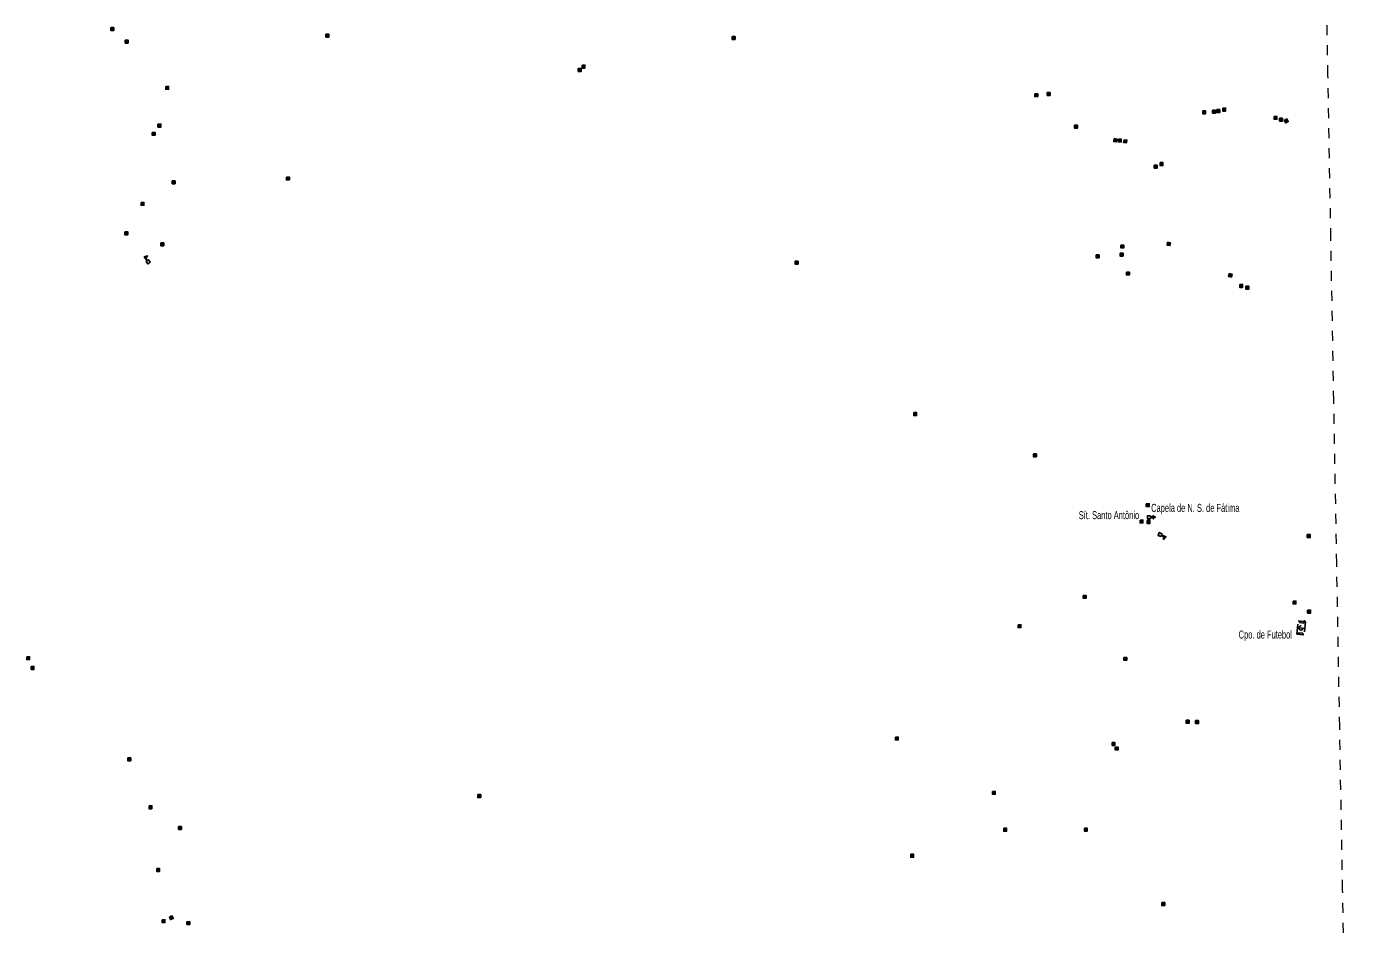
# Model space of a CAD drawing. Extents: x 220.8 to 246.7, y 7287.6 to 7315.8.
# Drawn here: x 233.32 to 246.65, y 7297.47 to 7306.49 of the extents above; entities that cross this region are included whole.
import ezdxf
from ezdxf.enums import TextEntityAlignment as Align

# ---------------------------------------------------------------- set-up
doc = ezdxf.new("R2010")
doc.units = 0
doc.header["$LTSCALE"] = 0.032
doc.header["$PDMODE"] = 32
doc.header["$PDSIZE"] = 0.016
doc.linetypes.add('MEDIUM_DASHED', pattern=[4.5, 3, -1.5])
doc.linetypes.add('SHORT_DASHED', pattern=[2.7, 1.5, -1.2])
for name, color, linetype, lineweight in [('14', 7, 'MEDIUM_DASHED', 25), ('2', 7, 'Continuous', 25), ('4', 7, 'Continuous', 25), ('58', 7, 'SHORT_DASHED', 13), ('6', 7, 'Continuous', 25)]:
    doc.layers.add(name, color=color, linetype=linetype, lineweight=lineweight)
doc.layers.add('61', color=7, linetype='Continuous')

msp = doc.modelspace()

# ---------------------------------------------------------------- hatches: boundary and pattern name
at = {"layer": '2'}
for points in [[(234.163, 7306.4822), (234.192, 7306.4822), (234.192, 7306.4532), (234.163, 7306.4532)], [(234.3069, 7306.3565), (234.3359, 7306.3565), (234.3359, 7306.3275), (234.3069, 7306.3275)], [(236.3128, 7306.416), (236.3418, 7306.416), (236.3418, 7306.387), (236.3128, 7306.387)], [(240.3724, 7306.3926), (240.4014, 7306.3926), (240.4014, 7306.3636), (240.3724, 7306.3636)], [(238.8349, 7306.0722), (238.8639, 7306.0722), (238.8639, 7306.0432), (238.8349, 7306.0432)], [(238.8727, 7306.1069), (238.9017, 7306.1069), (238.9017, 7306.0779), (238.8727, 7306.0779)], [(234.7115, 7305.8939), (234.7405, 7305.8939), (234.7405, 7305.8649), (234.7115, 7305.8649)], [(243.3974, 7305.8206), (243.4264, 7305.8206), (243.4264, 7305.7916), (243.3974, 7305.7916)], [(243.5214, 7305.8325), (243.5504, 7305.8325), (243.5504, 7305.8035), (243.5214, 7305.8035)], [(245.0755, 7305.6496), (245.1045, 7305.6496), (245.1045, 7305.6206), (245.0755, 7305.6206)], [(245.1738, 7305.6557), (245.2028, 7305.6557), (245.2028, 7305.6267), (245.1738, 7305.6267)], [(245.2168, 7305.6619), (245.2458, 7305.6619), (245.2458, 7305.6329), (245.2168, 7305.6329)], [(245.2752, 7305.6772), (245.3042, 7305.6772), (245.3042, 7305.6482), (245.2752, 7305.6482)], [(234.6341, 7305.517), (234.6631, 7305.517), (234.6631, 7305.488), (234.6341, 7305.488)], [(245.7883, 7305.5943), (245.8173, 7305.5943), (245.8173, 7305.5653), (245.7883, 7305.5653)], [(245.8436, 7305.5758), (245.8726, 7305.5758), (245.8726, 7305.5468), (245.8436, 7305.5468)], [(245.8912, 7305.5544), (245.9166, 7305.5685), (245.9307, 7305.5431), (245.9053, 7305.529)], [(234.5767, 7305.4346), (234.6057, 7305.4346), (234.6057, 7305.4056), (234.5767, 7305.4056)], [(243.7956, 7305.5058), (243.8246, 7305.5058), (243.8246, 7305.4768), (243.7956, 7305.4768)], [(244.1905, 7305.3718), (244.2191, 7305.3674), (244.2147, 7305.3387), (244.186, 7305.3432)], [(244.2329, 7305.3681), (244.2619, 7305.3681), (244.2619, 7305.3391), (244.2329, 7305.3391)], [(244.289, 7305.3614), (244.3176, 7305.357), (244.3132, 7305.3283), (244.2845, 7305.3328)], [(244.6495, 7305.1319), (244.6785, 7305.1319), (244.6785, 7305.1029), (244.6495, 7305.1029)], [(235.9185, 7304.9875), (235.9475, 7304.9875), (235.9475, 7304.9585), (235.9185, 7304.9585)], [(244.5905, 7305.1057), (244.6195, 7305.1057), (244.6195, 7305.0767), (244.5905, 7305.0767)], [(234.7767, 7304.9495), (234.8057, 7304.9495), (234.8057, 7304.9205), (234.7767, 7304.9205)], [(234.465, 7304.7345), (234.494, 7304.7345), (234.494, 7304.7055), (234.465, 7304.7055)], [(234.3027, 7304.4404), (234.3317, 7304.4404), (234.3317, 7304.4114), (234.3027, 7304.4114)], [(234.6625, 7304.3307), (234.6915, 7304.3307), (234.6915, 7304.3017), (234.6625, 7304.3017)], [(244.725, 7304.3365), (244.7535, 7304.3314), (244.7484, 7304.3029), (244.7199, 7304.3079)], [(244.0104, 7304.2097), (244.0394, 7304.2097), (244.0394, 7304.1807), (244.0104, 7304.1807)], [(244.2502, 7304.2273), (244.2792, 7304.2273), (244.2792, 7304.1983), (244.2502, 7304.1983)], [(244.2577, 7304.3081), (244.2867, 7304.3081), (244.2867, 7304.2791), (244.2577, 7304.2791)], [(241.0021, 7304.1463), (241.0311, 7304.1463), (241.0311, 7304.1173), (241.0021, 7304.1173)], [(244.3133, 7304.038), (244.3423, 7304.038), (244.3423, 7304.009), (244.3133, 7304.009)], [(245.3404, 7304.022), (245.3686, 7304.0152), (245.3619, 7303.987), (245.3336, 7303.9938)], [(245.4453, 7303.9138), (245.4743, 7303.9138), (245.4743, 7303.8848), (245.4453, 7303.8848)], [(245.5074, 7303.8954), (245.5364, 7303.8954), (245.5364, 7303.8664), (245.5074, 7303.8664)], [(242.1867, 7302.6326), (242.2157, 7302.6326), (242.2157, 7302.6036), (242.1867, 7302.6036)], [(243.3838, 7302.2199), (243.4128, 7302.2199), (243.4128, 7302.1909), (243.3838, 7302.1909)], [(244.512, 7301.7213), (244.541, 7301.7213), (244.541, 7301.6923), (244.512, 7301.6923)], [(244.4492, 7301.558), (244.4782, 7301.558), (244.4782, 7301.529), (244.4492, 7301.529)], [(244.5196, 7301.553), (244.5486, 7301.553), (244.5486, 7301.524), (244.5196, 7301.524)], [(246.1207, 7301.4125), (246.1497, 7301.4125), (246.1497, 7301.3835), (246.1207, 7301.3835)], [(243.8815, 7300.8051), (243.9105, 7300.8051), (243.9105, 7300.7761), (243.8815, 7300.7761)], [(245.9785, 7300.7483), (246.0075, 7300.7483), (246.0075, 7300.7193), (245.9785, 7300.7193)], [(246.1238, 7300.6577), (246.1528, 7300.6577), (246.1528, 7300.6287), (246.1238, 7300.6287)], [(243.2299, 7300.5118), (243.2589, 7300.5118), (243.2589, 7300.4828), (243.2299, 7300.4828)], [(233.3219, 7300.1924), (233.3509, 7300.1924), (233.3509, 7300.1634), (233.3219, 7300.1634)], [(244.2874, 7300.1855), (244.3164, 7300.1855), (244.3164, 7300.1565), (244.2874, 7300.1565)], [(233.3657, 7300.0942), (233.3947, 7300.0942), (233.3947, 7300.0652), (233.3657, 7300.0652)], [(244.9095, 7299.5566), (244.9385, 7299.5566), (244.9385, 7299.5276), (244.9095, 7299.5276)], [(245.0047, 7299.5532), (245.0337, 7299.5532), (245.0337, 7299.5242), (245.0047, 7299.5242)], [(242.0044, 7299.3892), (242.0334, 7299.3892), (242.0334, 7299.3602), (242.0044, 7299.3602)], [(244.1694, 7299.3339), (244.1984, 7299.3339), (244.1984, 7299.3049), (244.1694, 7299.3049)], [(244.2012, 7299.2886), (244.2302, 7299.2886), (244.2302, 7299.2596), (244.2012, 7299.2596)], [(234.3326, 7299.1809), (234.3616, 7299.1809), (234.3616, 7299.1519), (234.3326, 7299.1519)], [(237.8307, 7298.8131), (237.8597, 7298.8131), (237.8597, 7298.7841), (237.8307, 7298.7841)], [(242.9736, 7298.8453), (243.0026, 7298.8453), (243.0026, 7298.8163), (242.9736, 7298.8163)], [(234.5451, 7298.7013), (234.5741, 7298.7013), (234.5741, 7298.6723), (234.5451, 7298.6723)], [(234.8394, 7298.4942), (234.8684, 7298.4942), (234.8684, 7298.4652), (234.8394, 7298.4652)], [(243.0868, 7298.4763), (243.1158, 7298.4763), (243.1158, 7298.4473), (243.0868, 7298.4473)], [(243.8929, 7298.4772), (243.9219, 7298.4772), (243.9219, 7298.4482), (243.8929, 7298.4482)], [(242.157, 7298.2163), (242.186, 7298.2163), (242.186, 7298.1873), (242.157, 7298.1873)], [(234.6214, 7298.0745), (234.6504, 7298.0745), (234.6504, 7298.0455), (234.6214, 7298.0455)], [(244.6666, 7297.7332), (244.6956, 7297.7332), (244.6956, 7297.7042), (244.6666, 7297.7042)], [(234.6745, 7297.5628), (234.7035, 7297.5628), (234.7035, 7297.5338), (234.6745, 7297.5338)], [(234.7482, 7297.5899), (234.7752, 7297.6007), (234.786, 7297.5738), (234.7591, 7297.563)], [(234.9227, 7297.5428), (234.9517, 7297.5428), (234.9517, 7297.5138), (234.9227, 7297.5138)]]:
    msp.add_hatch(color=256, dxfattribs=at).paths.add_polyline_path(points)

# ---------------------------------------------------------------- linework, layer by layer
at = {"layer": '14'}
for p, q in [((246.0952, 7300.4754), (246.0227, 7300.4841)), ((246.0431, 7300.5333), (246.0448, 7300.5475)), ((246.0431, 7300.5333), (246.0872, 7300.528)), ((246.0466, 7300.5472), (246.0463, 7300.5476)), ((246.0889, 7300.5422), (246.0872, 7300.528)), ((246.0926, 7300.5418), (246.0926, 7300.5417)), ((246.029, 7300.4173), (246.0307, 7300.4315)), ((246.0749, 7300.4262), (246.0307, 7300.4315)), ((246.0749, 7300.4262), (246.0732, 7300.4119))]:
    msp.add_line(p, q, dxfattribs=at)
msp.add_lwpolyline([(246.0306, 7300.5492), (246.1031, 7300.5405), (246.0874, 7300.4102), (246.0148, 7300.419)], close=True, dxfattribs=at)
msp.add_circle((246.0589, 7300.4797), 0.0212, dxfattribs=at)
msp.add_point((246.0923, 7300.5418), dxfattribs=at)
at = {"layer": '2'}
for points in [[(234.163, 7306.4822), (234.192, 7306.4822), (234.192, 7306.4532), (234.163, 7306.4532)], [(234.3069, 7306.3565), (234.3359, 7306.3565), (234.3359, 7306.3275), (234.3069, 7306.3275)], [(236.3128, 7306.416), (236.3418, 7306.416), (236.3418, 7306.387), (236.3128, 7306.387)], [(240.3724, 7306.3926), (240.4014, 7306.3926), (240.4014, 7306.3636), (240.3724, 7306.3636)], [(238.8349, 7306.0722), (238.8639, 7306.0722), (238.8639, 7306.0432), (238.8349, 7306.0432)], [(238.8727, 7306.1069), (238.9017, 7306.1069), (238.9017, 7306.0779), (238.8727, 7306.0779)], [(234.7115, 7305.8939), (234.7405, 7305.8939), (234.7405, 7305.8649), (234.7115, 7305.8649)], [(243.3974, 7305.8206), (243.4264, 7305.8206), (243.4264, 7305.7916), (243.3974, 7305.7916)], [(243.5214, 7305.8325), (243.5504, 7305.8325), (243.5504, 7305.8035), (243.5214, 7305.8035)], [(245.0755, 7305.6496), (245.1045, 7305.6496), (245.1045, 7305.6206), (245.0755, 7305.6206)], [(245.1738, 7305.6557), (245.2028, 7305.6557), (245.2028, 7305.6267), (245.1738, 7305.6267)], [(245.2168, 7305.6619), (245.2458, 7305.6619), (245.2458, 7305.6329), (245.2168, 7305.6329)], [(245.2752, 7305.6772), (245.3042, 7305.6772), (245.3042, 7305.6482), (245.2752, 7305.6482)], [(234.6341, 7305.517), (234.6631, 7305.517), (234.6631, 7305.488), (234.6341, 7305.488)], [(245.7883, 7305.5943), (245.8173, 7305.5943), (245.8173, 7305.5653), (245.7883, 7305.5653)], [(245.8436, 7305.5758), (245.8726, 7305.5758), (245.8726, 7305.5468), (245.8436, 7305.5468)], [(245.8912, 7305.5544), (245.9166, 7305.5685), (245.9307, 7305.5431), (245.9053, 7305.529)], [(234.5767, 7305.4346), (234.6057, 7305.4346), (234.6057, 7305.4056), (234.5767, 7305.4056)], [(243.7956, 7305.5058), (243.8246, 7305.5058), (243.8246, 7305.4768), (243.7956, 7305.4768)], [(244.1905, 7305.3718), (244.2191, 7305.3674), (244.2147, 7305.3387), (244.186, 7305.3432)], [(244.2329, 7305.3681), (244.2619, 7305.3681), (244.2619, 7305.3391), (244.2329, 7305.3391)], [(244.289, 7305.3614), (244.3176, 7305.357), (244.3132, 7305.3283), (244.2845, 7305.3328)], [(244.6495, 7305.1319), (244.6785, 7305.1319), (244.6785, 7305.1029), (244.6495, 7305.1029)], [(235.9185, 7304.9875), (235.9475, 7304.9875), (235.9475, 7304.9585), (235.9185, 7304.9585)], [(244.5905, 7305.1057), (244.6195, 7305.1057), (244.6195, 7305.0767), (244.5905, 7305.0767)], [(234.7767, 7304.9495), (234.8057, 7304.9495), (234.8057, 7304.9205), (234.7767, 7304.9205)], [(234.465, 7304.7345), (234.494, 7304.7345), (234.494, 7304.7055), (234.465, 7304.7055)], [(234.3027, 7304.4404), (234.3317, 7304.4404), (234.3317, 7304.4114), (234.3027, 7304.4114)], [(234.6625, 7304.3307), (234.6915, 7304.3307), (234.6915, 7304.3017), (234.6625, 7304.3017)], [(244.725, 7304.3365), (244.7535, 7304.3314), (244.7484, 7304.3029), (244.7199, 7304.3079)], [(244.0104, 7304.2097), (244.0394, 7304.2097), (244.0394, 7304.1807), (244.0104, 7304.1807)], [(244.2502, 7304.2273), (244.2792, 7304.2273), (244.2792, 7304.1983), (244.2502, 7304.1983)], [(244.2577, 7304.3081), (244.2867, 7304.3081), (244.2867, 7304.2791), (244.2577, 7304.2791)], [(241.0021, 7304.1463), (241.0311, 7304.1463), (241.0311, 7304.1173), (241.0021, 7304.1173)], [(244.3133, 7304.038), (244.3423, 7304.038), (244.3423, 7304.009), (244.3133, 7304.009)], [(245.3404, 7304.022), (245.3686, 7304.0152), (245.3619, 7303.987), (245.3336, 7303.9938)], [(245.4453, 7303.9138), (245.4743, 7303.9138), (245.4743, 7303.8848), (245.4453, 7303.8848)], [(245.5074, 7303.8954), (245.5364, 7303.8954), (245.5364, 7303.8664), (245.5074, 7303.8664)], [(242.1867, 7302.6326), (242.2157, 7302.6326), (242.2157, 7302.6036), (242.1867, 7302.6036)], [(243.3838, 7302.2199), (243.4128, 7302.2199), (243.4128, 7302.1909), (243.3838, 7302.1909)], [(244.512, 7301.7213), (244.541, 7301.7213), (244.541, 7301.6923), (244.512, 7301.6923)], [(244.4492, 7301.558), (244.4782, 7301.558), (244.4782, 7301.529), (244.4492, 7301.529)], [(244.5196, 7301.553), (244.5486, 7301.553), (244.5486, 7301.524), (244.5196, 7301.524)], [(246.1207, 7301.4125), (246.1497, 7301.4125), (246.1497, 7301.3835), (246.1207, 7301.3835)], [(243.8815, 7300.8051), (243.9105, 7300.8051), (243.9105, 7300.7761), (243.8815, 7300.7761)], [(245.9785, 7300.7483), (246.0075, 7300.7483), (246.0075, 7300.7193), (245.9785, 7300.7193)], [(246.1238, 7300.6577), (246.1528, 7300.6577), (246.1528, 7300.6287), (246.1238, 7300.6287)], [(243.2299, 7300.5118), (243.2589, 7300.5118), (243.2589, 7300.4828), (243.2299, 7300.4828)], [(233.3219, 7300.1924), (233.3509, 7300.1924), (233.3509, 7300.1634), (233.3219, 7300.1634)], [(244.2874, 7300.1855), (244.3164, 7300.1855), (244.3164, 7300.1565), (244.2874, 7300.1565)], [(233.3657, 7300.0942), (233.3947, 7300.0942), (233.3947, 7300.0652), (233.3657, 7300.0652)], [(244.9095, 7299.5566), (244.9385, 7299.5566), (244.9385, 7299.5276), (244.9095, 7299.5276)], [(245.0047, 7299.5532), (245.0337, 7299.5532), (245.0337, 7299.5242), (245.0047, 7299.5242)], [(242.0044, 7299.3892), (242.0334, 7299.3892), (242.0334, 7299.3602), (242.0044, 7299.3602)], [(244.1694, 7299.3339), (244.1984, 7299.3339), (244.1984, 7299.3049), (244.1694, 7299.3049)], [(244.2012, 7299.2886), (244.2302, 7299.2886), (244.2302, 7299.2596), (244.2012, 7299.2596)], [(234.3326, 7299.1809), (234.3616, 7299.1809), (234.3616, 7299.1519), (234.3326, 7299.1519)], [(237.8307, 7298.8131), (237.8597, 7298.8131), (237.8597, 7298.7841), (237.8307, 7298.7841)], [(242.9736, 7298.8453), (243.0026, 7298.8453), (243.0026, 7298.8163), (242.9736, 7298.8163)], [(234.5451, 7298.7013), (234.5741, 7298.7013), (234.5741, 7298.6723), (234.5451, 7298.6723)], [(234.8394, 7298.4942), (234.8684, 7298.4942), (234.8684, 7298.4652), (234.8394, 7298.4652)], [(243.0868, 7298.4763), (243.1158, 7298.4763), (243.1158, 7298.4473), (243.0868, 7298.4473)], [(243.8929, 7298.4772), (243.9219, 7298.4772), (243.9219, 7298.4482), (243.8929, 7298.4482)], [(242.157, 7298.2163), (242.186, 7298.2163), (242.186, 7298.1873), (242.157, 7298.1873)], [(234.6214, 7298.0745), (234.6504, 7298.0745), (234.6504, 7298.0455), (234.6214, 7298.0455)], [(244.6666, 7297.7332), (244.6956, 7297.7332), (244.6956, 7297.7042), (244.6666, 7297.7042)], [(234.6745, 7297.5628), (234.7035, 7297.5628), (234.7035, 7297.5338), (234.6745, 7297.5338)], [(234.7482, 7297.5899), (234.7752, 7297.6007), (234.786, 7297.5738), (234.7591, 7297.563)], [(234.9227, 7297.5428), (234.9517, 7297.5428), (234.9517, 7297.5138), (234.9227, 7297.5138)]]:
    msp.add_lwpolyline(points, close=True, dxfattribs=at)
at = {"layer": '4'}
for points in [[(234.525, 7304.1503), (234.4965, 7304.1895), (234.5307, 7304.2), (234.5136, 7304.1743), (234.5289, 7304.1532)], [(234.5289, 7304.1532), (234.5387, 7304.1604), (234.5558, 7304.1369), (234.5325, 7304.1198), (234.5153, 7304.1433), (234.525, 7304.1503)], [(244.661, 7301.4055), (244.6563, 7301.3944), (244.6295, 7301.4056), (244.6408, 7301.4323), (244.6675, 7301.4211), (244.6628, 7301.41)], [(244.6628, 7301.41), (244.7075, 7301.3913), (244.6837, 7301.3645), (244.685, 7301.3954), (244.661, 7301.4055)]]:
    msp.add_lwpolyline(points, dxfattribs=at)
at = {"layer": '58'}
msp.add_lwpolyline([(246.6507, 7288.0853), (246.6212, 7289.7146), (246.5917, 7291.3439), (246.5622, 7292.9732), (246.5328, 7294.6024), (246.5034, 7296.2317), (246.4739, 7297.861), (246.4446, 7299.4903), (246.4152, 7301.1196), (246.3858, 7302.7489), (246.3565, 7304.3782), (246.3272, 7306.0075), (246.2979, 7307.6367), (246.2685, 7309.266), (246.2393, 7310.8953), (246.21, 7312.5246), (246.1808, 7314.1539), (246.1516, 7315.7832)], dxfattribs=at)
at = {"layer": '6'}
for points in [[(244.5523, 7301.5843), (244.5523, 7301.5722), (244.5233, 7301.5722), (244.5233, 7301.6012), (244.5523, 7301.6012), (244.5523, 7301.5891)], [(244.5523, 7301.5891), (244.5794, 7301.5891), (244.5794, 7301.6012), (244.5843, 7301.6012), (244.5843, 7301.5891), (244.6007, 7301.5891), (244.6007, 7301.5843), (244.5843, 7301.5843), (244.5843, 7301.5722), (244.5794, 7301.5722), (244.5794, 7301.5843), (244.5523, 7301.5843)]]:
    msp.add_lwpolyline(points, dxfattribs=at)

# ---------------------------------------------------------------- texts
at = {"layer": '61', "width": 0.7}
for s, p in [('Sít. Santo Antônio', (244.4405, 7301.5674)), ('Cpo. de Futebol', (245.9672, 7300.3736))]:
    msp.add_text(s, height=0.08, dxfattribs=at).set_placement(p, align=Align.RIGHT)
msp.add_text('Capela de N. S. de Fátima', height=0.08, dxfattribs=at).set_placement((244.5598, 7301.6403))

doc.saveas('drawing.dxf')
